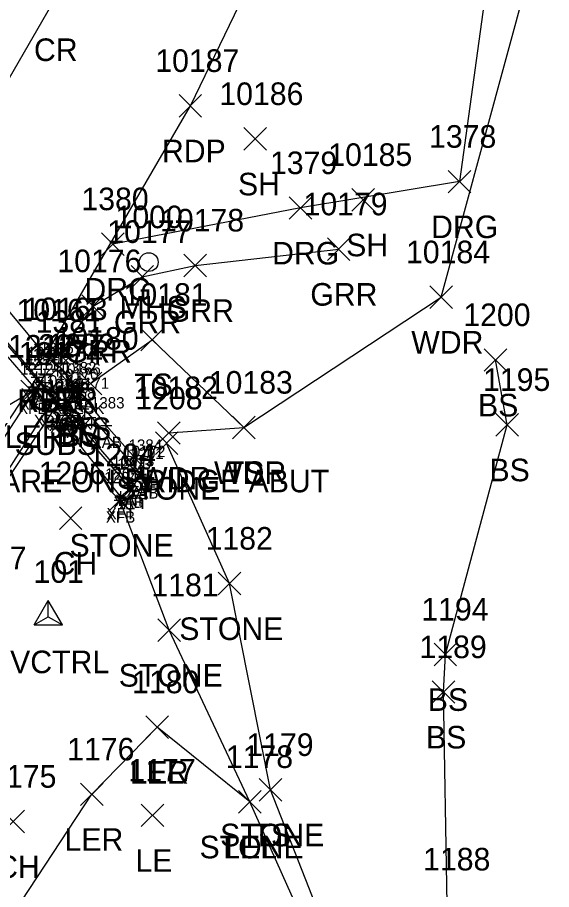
# Model space of a CAD drawing. Extents: x 1651685 to 1653558, y 889533 to 891085.
# Drawn here: x 1652719.8 to 1652767.1, y 890214.6 to 890291.8 of the extents above; entities that cross this region are included whole.
import ezdxf

# ---------------------------------------------------------------- set-up
doc = ezdxf.new("R2010")
doc.units = 0
for name, color, linetype in [('B_A', 7, 'Continuous'), ('B_I', 7, 'Continuous'), ('B_TIC', 7, 'Continuous'), ('BB', 7, 'Continuous'), ('BELB', 7, 'Continuous'), ('BFT', 7, 'Continuous'), ('BR', 7, 'Continuous'), ('BSE', 7, 'Continuous'), ('BSUBM', 7, 'Continuous'), ('C_A', 7, 'Continuous'), ('C_C', 7, 'Continuous'), ('C_I', 7, 'Continuous'), ('CPBM', 7, 'Continuous'), ('CPSM', 7, 'Continuous'), ('L_A', 7, 'Continuous'), ('L_I', 7, 'Continuous'), ('L_TIC', 7, 'Continuous'), ('LARO', 7, 'Continuous'), ('LASF', 7, 'Continuous'), ('LAWA', 7, 'Continuous'), ('LELB', 7, 'Continuous'), ('P_A', 7, 'Continuous'), ('P_I', 7, 'Continuous'), ('P_TIC', 7, 'Continuous'), ('PET', 7, 'Continuous'), ('PRC', 7, 'Continuous'), ('R_A', 7, 'Continuous'), ('R_I', 7, 'Continuous'), ('R_TIC', 7, 'Continuous'), ('RDG', 7, 'Continuous'), ('RGR', 7, 'Continuous'), ('U_A', 7, 'Continuous'), ('U_I', 7, 'Continuous'), ('U_TIC', 7, 'Continuous'), ('USA', 7, 'Continuous'), ('USMH', 7, 'Continuous')]:
    doc.layers.add(name, color=color, linetype=linetype)

msp = doc.modelspace()

# ---------------------------------------------------------------- linework, layer by layer
at = {"layer": 'B_TIC'}
for p, q in [((1652723.415, 890260.555), (1652723.491, 890260.555)), ((1652721.561, 890259.987), (1652721.636, 890259.987)), ((1652721.754, 890259.535), (1652721.83, 890259.535)), ((1652722.287, 890260.183), (1652722.363, 890260.183)), ((1652721.13, 890258.721), (1652721.206, 890258.721)), ((1652721.284, 890259.118), (1652721.36, 890259.118)), ((1652725.2, 890258.835), (1652725.276, 890258.835)), ((1652724.896, 890258.227), (1652724.972, 890258.227)), ((1652725.095, 890258.712), (1652725.171, 890258.712)), ((1652723.449, 890257.661), (1652723.524, 890257.661)), ((1652723.87, 890257.21), (1652723.946, 890257.21)), ((1652723.979, 890257.346), (1652724.055, 890257.346)), ((1652725.502, 890257.455), (1652725.577, 890257.455)), ((1652724.028, 890257.065), (1652724.103, 890257.065)), ((1652724.597, 890256.592), (1652724.673, 890256.592)), ((1652724.597, 890256.592), (1652724.673, 890256.592)), ((1652727.689, 890255.717), (1652727.764, 890255.717)), ((1652731.017, 890251.971), (1652731.093, 890251.971)), ((1652730.771, 890251.411), (1652730.846, 890251.411)), ((1652730.914, 890251.239), (1652730.989, 890251.239)), ((1652729.613, 890250.415), (1652729.688, 890250.415)), ((1652729.782, 890250.582), (1652729.857, 890250.582)), ((1652729.782, 890250.582), (1652729.857, 890250.582)), ((1652730.047, 890250.298), (1652730.122, 890250.298)), ((1652728.901, 890249.098), (1652728.976, 890249.098)), ((1652728.982, 890249.404), (1652729.058, 890249.404))]:
    msp.add_line(p, q, dxfattribs=at)
for points in [[(1652723.412, 890260.055), (1652723.412, 890261.055)], [(1652721.557, 890259.487), (1652721.557, 890260.487)], [(1652722.284, 890259.683), (1652722.284, 890260.683)], [(1652722.912, 890260.555), (1652723.912, 890260.555)], [(1652721.057, 890259.987), (1652722.057, 890259.987)], [(1652721.251, 890259.535), (1652722.251, 890259.535)], [(1652721.281, 890258.618), (1652721.281, 890259.618)], [(1652721.751, 890259.035), (1652721.751, 890260.035)], [(1652721.784, 890260.183), (1652722.784, 890260.183)], [(1652720.627, 890258.721), (1652721.627, 890258.721)], [(1652720.781, 890259.118), (1652721.781, 890259.118)], [(1652721.127, 890258.221), (1652721.127, 890259.221)], [(1652724.697, 890258.835), (1652725.697, 890258.835)], [(1652724.893, 890257.727), (1652724.893, 890258.727)], [(1652725.092, 890258.212), (1652725.092, 890259.212)], [(1652725.197, 890258.335), (1652725.197, 890259.335)], [(1652723.445, 890257.161), (1652723.445, 890258.161)], [(1652724.393, 890258.227), (1652725.393, 890258.227)], [(1652724.592, 890258.712), (1652725.592, 890258.712)], [(1652725.498, 890256.955), (1652725.498, 890257.955)], [(1652722.945, 890257.661), (1652723.945, 890257.661)], [(1652723.367, 890257.21), (1652724.367, 890257.21)], [(1652723.476, 890257.346), (1652724.476, 890257.346)], [(1652723.867, 890256.71), (1652723.867, 890257.71)], [(1652723.976, 890256.846), (1652723.976, 890257.846)], [(1652724.024, 890256.565), (1652724.024, 890257.565)], [(1652724.998, 890257.455), (1652725.998, 890257.455)], [(1652723.524, 890257.065), (1652724.524, 890257.065)], [(1652724.094, 890256.592), (1652725.094, 890256.592)], [(1652724.094, 890256.592), (1652725.094, 890256.592)], [(1652724.594, 890256.092), (1652724.594, 890257.092)], [(1652724.594, 890256.092), (1652724.594, 890257.092)], [(1652727.185, 890255.717), (1652728.185, 890255.717)], [(1652727.685, 890255.217), (1652727.685, 890256.217)], [(1652730.514, 890251.971), (1652731.514, 890251.971)], [(1652730.767, 890250.911), (1652730.767, 890251.911)], [(1652731.014, 890251.471), (1652731.014, 890252.471)], [(1652729.778, 890250.082), (1652729.778, 890251.082)], [(1652729.778, 890250.082), (1652729.778, 890251.082)], [(1652730.267, 890251.411), (1652731.267, 890251.411)], [(1652730.41, 890251.239), (1652731.41, 890251.239)], [(1652730.91, 890250.739), (1652730.91, 890251.739)], [(1652729.109, 890250.415), (1652730.109, 890250.415)], [(1652729.278, 890250.582), (1652730.278, 890250.582)], [(1652729.278, 890250.582), (1652730.278, 890250.582)], [(1652729.543, 890250.298), (1652730.543, 890250.298)], [(1652729.609, 890249.915), (1652729.609, 890250.915)], [(1652730.043, 890249.798), (1652730.043, 890250.798)], [(1652728.897, 890248.598), (1652728.897, 890249.598)], [(1652728.979, 890248.904), (1652728.979, 890249.904)], [(1652728.397, 890249.098), (1652729.397, 890249.098)], [(1652728.479, 890249.404), (1652729.479, 890249.404)]]:
    msp.add_lwpolyline(points, dxfattribs=at)
at = {"layer": 'BB'}
msp.add_lwpolyline([(1652721.557, 890259.987), (1652708.489, 890240.052)], dxfattribs=at)
at = {"layer": 'BELB'}
msp.add_lwpolyline([(1652709.172, 890236.253), (1652723.445, 890257.661), (1652723.976, 890257.346), (1652725.092, 890258.712), (1652723.412, 890260.555)], dxfattribs=at)
at = {"layer": 'BFT'}
msp.add_lwpolyline([(1652730.043, 890250.298), (1652728.979, 890249.404), (1652721.281, 890259.118), (1652713.404, 890268.228), (1652713.874, 890268.743)], dxfattribs=at)
at = {"layer": 'BR'}
msp.add_lwpolyline([(1652708.535, 890239.146), (1652722.284, 890260.183)], dxfattribs=at)
at = {"layer": 'BSE'}
msp.add_lwpolyline([(1652702.322, 890282.616), (1652723.867, 890257.21)], dxfattribs=at)
at = {"layer": 'BSUBM'}
for points in [[(1652730.91, 890251.239), (1652729.609, 890250.415), (1652721.751, 890259.535), (1652713.874, 890268.743), (1652713.817, 890268.822), (1652702.155, 890282.607), (1652701.912, 890282.515), (1652698.364, 890286.414), (1652698.385, 890299.877), (1652698.504, 890301.956), (1652700.485, 890302.125)], [(1652725.197, 890258.835), (1652727.685, 890255.717), (1652731.014, 890251.971)], [(1652724.594, 890256.592), (1652724.024, 890257.065), (1652724.893, 890258.227), (1652725.498, 890257.455), (1652730.767, 890251.411), (1652729.778, 890250.582)], [(1652724.594, 890256.592), (1652729.778, 890250.582)]]:
    msp.add_lwpolyline(points, dxfattribs=at)
at = {"layer": 'CPBM'}
for p, q in [((1652724.505, 890258.29), (1652724.505, 890259.29)), ((1652724.505, 890259.29), (1652725.505, 890259.29)), ((1652725.008, 890258.79), (1652725.008, 890258.79)), ((1652725.008, 890258.79), (1652725.008, 890258.79)), ((1652725.505, 890259.29), (1652725.505, 890258.29)), ((1652725.505, 890258.29), (1652724.505, 890258.29))]:
    msp.add_line(p, q, dxfattribs=at)
at = {"layer": 'CPSM'}
for p, q in [((1652721.312, 890238.053), (1652722.562, 890240.218)), ((1652723.812, 890238.053), (1652722.562, 890240.218)), ((1652722.563, 890238.774), (1652722.562, 890240.218)), ((1652721.312, 890238.053), (1652722.563, 890238.774)), ((1652722.563, 890238.774), (1652722.563, 890238.774)), ((1652722.563, 890238.774), (1652723.812, 890238.053)), ((1652721.312, 890238.053), (1652723.812, 890238.053))]:
    msp.add_line(p, q, dxfattribs=at)
at = {"layer": 'L_TIC'}
for points in [[(1652739.864, 890280.082), (1652741.864, 890282.082)], [(1652741.864, 890280.082), (1652739.864, 890282.082)], [(1652749.443, 890274.688), (1652751.443, 890276.688)], [(1652751.443, 890274.688), (1652749.443, 890276.688)], [(1652756.329, 890266.071), (1652758.329, 890268.071)], [(1652758.329, 890266.071), (1652756.329, 890268.071)], [(1652730.761, 890262.304), (1652732.761, 890264.304)], [(1652732.761, 890262.304), (1652730.761, 890264.304)], [(1652722.567, 890259.912), (1652724.567, 890261.912)], [(1652724.567, 890259.912), (1652722.567, 890261.912)], [(1652761.155, 890260.509), (1652763.155, 890262.509)], [(1652763.155, 890260.509), (1652761.155, 890262.509)], [(1652725.309, 890258.416), (1652727.309, 890260.416)], [(1652727.309, 890258.416), (1652725.309, 890260.416)], [(1652720.127, 890257.721), (1652722.127, 890259.721)], [(1652722.127, 890257.721), (1652720.127, 890259.721)], [(1652724.197, 890257.835), (1652726.197, 890259.835)], [(1652726.197, 890257.835), (1652724.197, 890259.835)], [(1652738.873, 890254.528), (1652740.873, 890256.528)], [(1652740.873, 890254.528), (1652738.873, 890256.528)], [(1652738.873, 890254.528), (1652740.873, 890256.528)], [(1652740.873, 890254.528), (1652738.873, 890256.528)], [(1652762.171, 890254.767), (1652764.171, 890256.767)], [(1652764.171, 890254.767), (1652762.171, 890256.767)], [(1652732.239, 890254.045), (1652734.239, 890256.045)], [(1652734.239, 890254.045), (1652732.239, 890256.045)], [(1652732.04, 890253.139), (1652734.04, 890255.139)], [(1652734.04, 890253.139), (1652732.04, 890255.139)], [(1652727.897, 890248.098), (1652729.897, 890250.098)], [(1652729.897, 890248.098), (1652727.897, 890250.098)], [(1652723.542, 890246.509), (1652725.542, 890248.509)], [(1652725.542, 890246.509), (1652723.542, 890248.509)], [(1652737.613, 890240.712), (1652739.613, 890242.712)], [(1652739.613, 890240.712), (1652737.613, 890242.712)], [(1652732.252, 890236.583), (1652734.252, 890238.583)], [(1652734.252, 890236.583), (1652732.252, 890238.583)], [(1652756.707, 890234.436), (1652758.707, 890236.436)], [(1652758.707, 890234.436), (1652756.707, 890236.436)], [(1652756.554, 890231.106), (1652758.554, 890233.106)], [(1652758.554, 890231.106), (1652756.554, 890233.106)], [(1652731.201, 890227.998), (1652733.201, 890229.998)], [(1652733.201, 890227.998), (1652731.201, 890229.998)], [(1652731.201, 890227.998), (1652733.201, 890229.998)], [(1652733.201, 890227.998), (1652731.201, 890229.998)], [(1652725.418, 890222.049), (1652727.418, 890224.049)], [(1652727.418, 890222.049), (1652725.418, 890224.049)], [(1652741.226, 890222.445), (1652743.226, 890224.445)], [(1652743.226, 890222.445), (1652741.226, 890224.445)], [(1652741.226, 890222.445), (1652743.226, 890224.445)], [(1652743.226, 890222.445), (1652741.226, 890224.445)], [(1652739.406, 890221.379), (1652741.406, 890223.379)], [(1652741.406, 890221.379), (1652739.406, 890223.379)], [(1652739.406, 890221.379), (1652741.406, 890223.379)], [(1652741.406, 890221.379), (1652739.406, 890223.379)], [(1652730.788, 890220.186), (1652732.788, 890222.186)], [(1652732.788, 890220.186), (1652730.788, 890222.186)], [(1652718.459, 890219.631), (1652720.459, 890221.631)], [(1652720.459, 890219.631), (1652718.459, 890221.631)]]:
    msp.add_lwpolyline(points, dxfattribs=at)
at = {"layer": 'LARO'}
for points in [[(1652721.127, 890258.721), (1652713.393, 890254.174), (1652704.778, 890264.349), (1652705.466, 890274.919)], [(1652741.291, 890109.75), (1652743.69, 890134.843), (1652747.37, 890143.521), (1652742.713, 890157.365), (1652736.668, 890166.137), (1652716.936, 890188.64), (1652716.703, 890208.338), (1652726.418, 890223.049), (1652732.201, 890228.998)], [(1652751.396, 890109.933), (1652753.404, 890128.345), (1652752.969, 890145.054), (1652756.278, 890157.715), (1652762.162, 890174.173), (1652750.723, 890181.882), (1652747.195, 890192.192), (1652746.952, 890207.758), (1652740.406, 890222.379), (1652732.201, 890228.998)]]:
    msp.add_lwpolyline(points, dxfattribs=at)
at = {"layer": 'LASF'}
for points in [[(1652742.226, 890223.445), (1652738.613, 890241.712), (1652733.04, 890254.139)], [(1652740.406, 890222.379), (1652733.252, 890237.583), (1652728.897, 890249.098)]]:
    msp.add_lwpolyline(points, dxfattribs=at)
at = {"layer": 'LAWA'}
msp.add_lwpolyline([(1652733.239, 890255.045), (1652739.873, 890255.528), (1652757.329, 890267.071), (1652768.835, 890309.355), (1652781.068, 890350.147), (1652797.707, 890393.693), (1652815.714, 890436.04), (1652825.054, 890456.619), (1652833.352, 890477.684), (1652833.388, 890492.3)], dxfattribs=at)
at = {"layer": 'LELB'}
for points in [[(1652726.309, 890259.416), (1652731.761, 890263.304), (1652739.873, 890255.528)], [(1652755.729, 890200.175), (1652757.867, 890213.308), (1652757.554, 890232.106), (1652757.707, 890235.436), (1652763.171, 890255.767), (1652762.155, 890261.509)], [(1652723.567, 890260.912), (1652725.197, 890258.835)], [(1652765.306, 890170.965), (1652754.362, 890182.738), (1652755.363, 890191.402), (1652748.091, 890208.473), (1652742.226, 890223.445)]]:
    msp.add_lwpolyline(points, dxfattribs=at)
at = {"layer": 'P_TIC'}
for points in [[(1652734.137, 890283.012), (1652736.137, 890285.012)], [(1652736.137, 890283.012), (1652734.137, 890285.012)], [(1652721.331, 890260.916), (1652723.331, 890262.916)], [(1652723.331, 890260.916), (1652721.331, 890262.916)]]:
    msp.add_lwpolyline(points, dxfattribs=at)
at = {"layer": 'PET'}
msp.add_lwpolyline([(1652703.162, 890284.218), (1652712.038, 890274.257), (1652722.331, 890261.916), (1652735.137, 890284.012), (1652751.621, 890318.115), (1652767.723, 890357.351), (1652783.179, 890400.145), (1652797.7, 890444.761), (1652815.977, 890499.358)], dxfattribs=at)
at = {"layer": 'PRC'}
msp.add_lwpolyline([(1652712.038, 890274.257), (1652722.864, 890292.979), (1652739.686, 890324.96), (1652756.287, 890362.602), (1652772.674, 890406.812), (1652786.214, 890448.938), (1652804.537, 890503.78)], dxfattribs=at)
at = {"layer": 'R_TIC'}
for points in [[(1652757.96, 890276.3), (1652759.96, 890278.3)], [(1652759.96, 890276.3), (1652757.96, 890278.3)], [(1652743.884, 890273.965), (1652745.884, 890275.965)], [(1652745.884, 890273.965), (1652743.884, 890275.965)], [(1652727.277, 890270.77), (1652729.277, 890272.77)], [(1652729.277, 890270.77), (1652727.277, 890272.77)], [(1652747.266, 890270.318), (1652749.266, 890272.318)], [(1652749.266, 890270.318), (1652747.266, 890272.318)], [(1652734.563, 890268.884), (1652736.563, 890270.884)], [(1652736.563, 890268.884), (1652734.563, 890270.884)], [(1652729.885, 890267.868), (1652731.885, 890269.868)], [(1652731.885, 890267.868), (1652729.885, 890269.868)], [(1652725.524, 890265.28), (1652727.524, 890267.28)], [(1652727.524, 890265.28), (1652725.524, 890267.28)], [(1652722.522, 890261.036), (1652724.522, 890263.036)], [(1652724.522, 890261.036), (1652722.522, 890263.036)]]:
    msp.add_lwpolyline(points, dxfattribs=at)
at = {"layer": 'RDG'}
msp.add_lwpolyline([(1652765.146, 890345.746), (1652764.722, 890328.25), (1652762.74, 890304.759), (1652758.96, 890277.3), (1652744.884, 890274.965), (1652728.277, 890271.77)], dxfattribs=at)
at = {"layer": 'RGR'}
msp.add_lwpolyline([(1652723.522, 890262.036), (1652726.524, 890266.28), (1652730.885, 890268.868), (1652735.563, 890269.884), (1652748.266, 890271.318)], dxfattribs=at)
at = {"layer": 'U_TIC'}
for points in [[(1652722.048, 890257.093), (1652724.048, 890259.093)], [(1652724.048, 890257.093), (1652722.048, 890259.093)]]:
    msp.add_lwpolyline(points, dxfattribs=at)
at = {"layer": 'USA'}
msp.add_lwpolyline([(1652723.048, 890258.093), (1652710.168, 890238)], dxfattribs=at)
at = {"layer": 'USMH'}
for p, q in [((1652731.452, 890270.174), (1652731.452, 890270.174)), ((1652732.285, 890270.174), (1652732.285, 890270.174))]:
    msp.add_line(p, q, dxfattribs=at)
msp.add_circle((1652731.452, 890270.174), 0.833, dxfattribs=at)

# ---------------------------------------------------------------- texts
at = {"layer": 'B_A'}
for s, p in [('XDECK', (1652721.255, 890258.555)), ('XBIB', (1652720.128, 890257.987)), ('XRF', (1652721.043, 890258.183)), ('XFT', (1652720.025, 890257.118)), ('XAB', (1652720.471, 890257.535)), ('XFB', (1652719.887, 890256.721)), ('XDECK', (1652722.934, 890256.712)), ('XAT', (1652723.597, 890256.227)), ('XAB', (1652723.917, 890256.835)), ('XDECK', (1652721.288, 890255.661)), ('XAT', (1652724.203, 890255.455)), ('XDECK', (1652721.818, 890255.346)), ('XBS', (1652722.607, 890255.21)), ('XAT', (1652722.729, 890255.065)), ('XAT', (1652723.298, 890254.592)), ('XAT', (1652723.298, 890254.592)), ('XAB', (1652726.406, 890253.717)), ('XAT', (1652729.472, 890249.411)), ('XAB', (1652729.631, 890249.239)), ('XAB', (1652729.734, 890249.971)), ('XAT', (1652728.483, 890248.582)), ('XAT', (1652728.483, 890248.582)), ('XAB', (1652728.33, 890248.415)), ('XFT', (1652728.788, 890248.298)), ('XFB', (1652727.657, 890247.098)), ('XFT', (1652727.723, 890247.404))]:
    msp.add_text(s, height=1, dxfattribs=at).set_placement(p)
at = {"layer": 'B_I'}
for s, p in [('10162', (1652720.709, 890261.683)), ('10167', (1652721.837, 890262.055)), ('1251', (1652720.494, 890261.487)), ('1210', (1652720.645, 890261.035)), ('1212', (1652720.064, 890260.221)), ('1211', (1652720.502, 890260.618)), ('10166', (1652723.489, 890260.212)), ('1382', (1652723.85, 890260.335)), ('10170', (1652723.298, 890259.727)), ('10164', (1652721.87, 890259.161)), ('10165', (1652722.401, 890258.846)), ('10169', (1652722.446, 890258.565)), ('1252', (1652722.52, 890258.71)), ('10171', (1652724.231, 890258.955)), ('10168', (1652723.019, 890258.092)), ('10168', (1652723.019, 890258.092)), ('1383', (1652726.339, 890257.217)), ('1384', (1652729.668, 890253.471)), ('10172', (1652729.216, 890252.911)), ('1201', (1652729.808, 890252.739)), ('1202', (1652728.223, 890251.915)), ('10173', (1652728.227, 890252.082)), ('10173', (1652728.227, 890252.082)), ('1203', (1652728.658, 890251.798)), ('1205', (1652727.593, 890250.904)), ('1204', (1652727.512, 890250.598))]:
    msp.add_text(s, height=1, dxfattribs=at).set_placement(p)
at = {"layer": 'C_A'}
for s, p in [('BM', (1652723.323, 890253.79)), ('HVCTRL', (1652717.256, 890233.774))]:
    msp.add_text(s, height=2, dxfattribs=at).set_placement(p)
at = {"layer": 'C_C'}
msp.add_text('CHISELED SQUARE ON BRIDGE ABUT', height=2, dxfattribs=at).set_placement((1652698.386, 890249.79))
at = {"layer": 'C_I'}
for s, p in [('2077', (1652721.669, 890261.79)), ('101', (1652721.256, 890241.774))]:
    msp.add_text(s, height=2, dxfattribs=at).set_placement(p)
at = {"layer": 'L_A'}
for s, p in [('SH', (1652739.352, 890276.082)), ('SH', (1652748.931, 890270.688)), ('WDR', (1652754.692, 890262.071)), ('TS', (1652730.17, 890258.304)), ('BS', (1652760.596, 890256.509)), ('BS', (1652722.008, 890255.912)), ('TS', (1652724.718, 890254.416)), ('LER', (1652718.71, 890253.721)), ('BS', (1652723.638, 890253.835)), ('TS', (1652738.283, 890250.528)), ('BS', (1652761.612, 890250.767)), ('WDR', (1652730.601, 890250.045)), ('WDR', (1652737.235, 890250.528)), ('STONE', (1652728.584, 890249.139)), ('STONE', (1652724.441, 890244.098)), ('CH', (1652723.03, 890242.509)), ('STONE', (1652734.156, 890236.712)), ('STONE', (1652728.795, 890232.583)), ('BS', (1652756.148, 890230.436)), ('BS', (1652755.995, 890227.106)), ('LER', (1652729.783, 890223.998)), ('LEL', (1652729.839, 890223.998)), ('STONE', (1652737.77, 890218.445)), ('TS', (1652740.636, 890218.445)), ('LER', (1652724.001, 890218.049)), ('STONE', (1652735.949, 890217.379)), ('LEL', (1652738.043, 890217.379)), ('LE', (1652730.276, 890216.186)), ('CH', (1652717.948, 890215.631))]:
    msp.add_text(s, height=2, dxfattribs=at).set_placement(p)
at = {"layer": 'L_I'}
for s, p in [('10186', (1652737.706, 890284.082)), ('10185', (1652747.341, 890278.688)), ('10184', (1652754.227, 890270.071)), ('10181', (1652729.226, 890266.304)), ('1200', (1652759.297, 890264.509)), ('1381', (1652721.442, 890263.912)), ('10180', (1652723.12, 890262.416)), ('1212', (1652719.001, 890261.721)), ('1382', (1652722.504, 890261.835)), ('10183', (1652736.771, 890258.528)), ('10183', (1652736.771, 890258.528)), ('1195', (1652761.045, 890258.767)), ('10182', (1652730.137, 890258.045)), ('1208', (1652730.269, 890257.139)), ('1204', (1652726.126, 890252.098)), ('1206', (1652721.716, 890250.509)), ('1182', (1652736.487, 890244.712)), ('1207', (1652714.682, 890242.976)), ('1181', (1652731.693, 890240.583)), ('1194', (1652755.582, 890238.436)), ('1189', (1652755.421, 890235.106)), ('1180', (1652729.988, 890231.998)), ('1180', (1652729.988, 890231.998)), ('1176', (1652724.237, 890226.049)), ('1179', (1652740.093, 890226.445)), ('1179', (1652740.093, 890226.445)), ('1178', (1652738.28, 890225.379)), ('1178', (1652738.28, 890225.379)), ('1175', (1652717.334, 890223.631)), ('1177', (1652729.662, 890224.186)), ('1188', (1652755.741, 890216.308))]:
    msp.add_text(s, height=2, dxfattribs=at).set_placement(p)
at = {"layer": 'P_A'}
for s, p in [('CR', (1652721.297, 890287.979)), ('RDP', (1652732.625, 890279.012)), ('RDP', (1652719.819, 890256.916))]:
    msp.add_text(s, height=2, dxfattribs=at).set_placement(p)
at = {"layer": 'P_I'}
for s, p in [('10187', (1652732.035, 890287.012)), ('10161', (1652719.749, 890264.916))]:
    msp.add_text(s, height=2, dxfattribs=at).set_placement(p)
at = {"layer": 'R_A'}
for s, p in [('DRG', (1652756.448, 890272.3)), ('DRG', (1652742.372, 890269.965)), ('DRG', (1652725.765, 890266.77)), ('GRR', (1652745.754, 890266.318)), ('GRR', (1652733.051, 890264.884)), ('GRR', (1652728.373, 890263.868)), ('GRR', (1652724.012, 890261.28)), ('GRR', (1652721.01, 890257.036))]:
    msp.add_text(s, height=2, dxfattribs=at).set_placement(p)
at = {"layer": 'R_I'}
for s, p in [('1378', (1652756.267, 890280.3)), ('1379', (1652742.184, 890277.965)), ('1380', (1652725.498, 890274.77)), ('10179', (1652745.156, 890274.318)), ('10178', (1652732.461, 890272.884)), ('10177', (1652727.783, 890271.868)), ('10176', (1652723.367, 890269.28)), ('10163', (1652720.372, 890265.036))]:
    msp.add_text(s, height=2, dxfattribs=at).set_placement(p)
at = {"layer": 'U_A'}
for s, p in [('MHS', (1652728.869, 890265.174)), ('SUBS', (1652719.583, 890253.093))]:
    msp.add_text(s, height=2, dxfattribs=at).set_placement(p)
at = {"layer": 'U_I'}
for s, p in [('1000', (1652728.515, 890273.174)), ('10174', (1652719.946, 890261.093))]:
    msp.add_text(s, height=2, dxfattribs=at).set_placement(p)

doc.saveas('drawing.dxf')
